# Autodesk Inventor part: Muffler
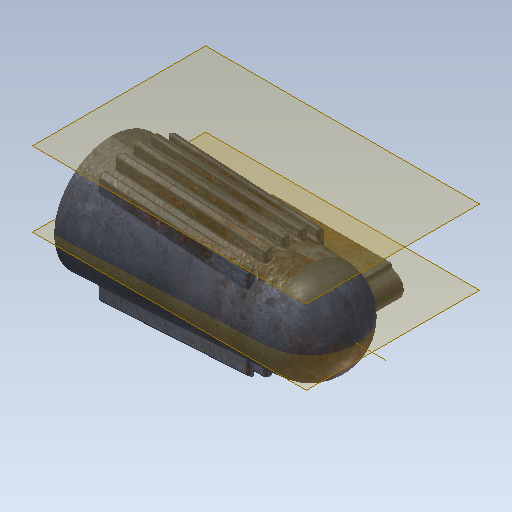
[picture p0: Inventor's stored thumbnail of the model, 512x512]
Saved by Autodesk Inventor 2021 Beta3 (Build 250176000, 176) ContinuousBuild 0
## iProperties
Created: 2012-08
Part Number: Muffler
Material: Aluminum 6061
Document SubType Name: Modeling
Designer: John
Density: 1 g/cm^3
Appearance: Oxidized
Author: John
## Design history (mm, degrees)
sketch "Sketch1"
  geometry: L1 (-24.257, -13.703)-(-24.257, -10.528) reference; L2 (-24.257, -10.528)-(-6.391, -10.528) reference; L3 (-6.391, -10.528)-(-6.391, -13.703) reference; L4 (-6.391, -13.703)-(-24.257, -13.703) reference; L5 (0, -7.62)-(0, -8.89) reference; L6 (0, -7.62)-(-30.48, -7.62) reference; L7 (-30.48, -7.62)-(-30.48, -8.89) reference; L8 (-30.48, -15.24)-(0, -15.24) reference; L9 (-5.756, -9.893)-(-24.892, -9.893); L10 (-24.892, -9.893)-(-24.892, -14.338); L11 (-24.892, -14.338)-(-5.756, -14.338); L12 (-5.756, -14.338)-(-5.756, -9.893); C1 r 1.638 at (0, -12.065) reference; C2 r 1.638 at (-30.48, -12.065) reference; A1 r 3.175 centre (-30.48, -12.065) between (-30.48, -8.89) and (-30.48, -15.24) reference; A2 r 3.175 centre (0, -12.065) between (0, -15.24) and (0, -8.89) reference; 1 further point
  constraints: 8 end point, 3 other
  dimensions: "d0" = 0.635 distance between parallel lines of L9 L2
  node "Reference1"
workplane "Work Plane1"
sketch "Sketch2"
  geometry: L1 (16.653, -4.445)-(-46.049, -4.445); L2 (-46.049, -4.445)-(-46.049, -18.969); L3 (-30.48, -15.24)-(0, -15.24) reference; L4 (-46.049, -18.969)-(5.151, -16.51); A1 r 12.082 centre (4.571, -4.442) between (5.151, -16.51) and (16.653, -4.445); 2 further points
  constraints: 6 end point, 2 point on circle, 1 centre point, 1 perpendicular, 1 tangent, 1 vertical
  dimensions: "d8" = 2.75 deg angle of L3 L4; "d9" = 1.27 distance from line of L3 L4.end; "d12" = 7.62 distance from line of L1 point (0, -12.065)
revolve "Revolution1" sketch "Sketch2" stored, may be unused: angle "d13" = 90 deg
shell "Shell2" dims "d17" = 1.27
extrude "Extrusion1" join sketch "Sketch1" stored distance "d15" = 25.4; taper "d16" = 0 deg
sketch "Sketch3"
  geometry: L1 (5.756, -14.338)-(5.756, -9.893) reference; L2 (5.756, -9.893)-(24.892, -9.893) reference; L3 (24.892, -9.893)-(24.892, -14.338) reference; L4 (24.892, -14.338)-(5.756, -14.338) reference; 1 further point
extrude "Extrusion2" cut sketch "Sketch3" stored distance "d18" = 25.4; taper "d19" = 0 deg
fillet "Fillet1" dims "d20" = 3.175
fillet "Fillet2" dims "d21" = 1.27
fillet "Fillet3" dims "d22" = 1.27
workplane "Work Plane3"
  workplane "Work Plane2"
sketch "Sketch4"
  geometry: L1 (-19.25, 9.843)-(19.25, 9.843); L2 (19.25, 9.843)-(19.25, 7.938); L3 (19.25, 7.938)-(-19.25, 7.938); L4 (-19.25, 7.938)-(-19.25, 9.843); L5 (-19.25, 5.398)-(19.25, 5.398); L6 (19.25, 5.398)-(19.25, 3.493); L7 (19.25, 3.493)-(-19.25, 3.492); L8 (-19.25, 3.492)-(-19.25, 5.398); L9 (-19.25, 0.953)-(19.25, 0.953); L10 (19.25, 0.953)-(19.25, -0.953); L11 (19.25, -0.953)-(-19.25, -0.953); L12 (-19.25, -0.953)-(-19.25, 0.953); L13 (-19.25, -3.493)-(19.25, -3.493); L14 (19.25, -3.493)-(19.25, -5.398); L15 (19.25, -5.398)-(-19.25, -5.398); L16 (-19.25, -5.398)-(-19.25, -3.493); L17 (-19.25, -7.938)-(19.25, -7.938); L18 (19.25, -7.938)-(19.25, -9.843); L19 (19.25, -9.843)-(-19.25, -9.843); L20 (-19.25, -9.843)-(-19.25, -7.938); L21 (-49.642, 0)-(38.14, 0) reference; L22 (25.6, -14.524)-(25.6, 14.524) reference; L23 (-25.6, -12.065)-(-25.6, 12.065) reference; 1 further point
  constraints: 40 end point, 10 parallel, 6 collinear, 6 equal length, 5 horizontal, 5 perpendicular
  dimensions: "d27" = 6.35 distance between parallel lines of L22 L10; "d28" = 6.35 distance between parallel lines of L23 L12 (= d27); "d29" = 2.54 distance between parallel lines of L9 L7; "d30" = 2.54 distance between parallel lines of L13 L11 (= d29); "d31" = 2.54 distance between parallel lines of L3 L5 (= d29); "d32" = 2.54 distance between parallel lines of L17 L15 (= d30); "d33" = 0.9525 distance between parallel lines of L9 L21 (= 0.5 x d34); "d34" = 1.905 distance of L9.end L10.end
emboss "Emboss1" sketch "Sketch4" dims "d25" = 2.54, "d26" = 0
mirror "Mirror2"
fillet "Fillet7" dims "d40" = 0.635
fillet "Fillet8" dims "d41" = 0.508
sketch "Sketch5"
  geometry: A1 r 3.175 centre (0, -12.065) between (-0.907, -9.022) and (0, -15.24) reference; A2 r 3.175 centre (30.48, -12.065) between (30.48, -15.24) and (31.387, -9.022) reference; 1 further point
hole "Hole1" sketch "Sketch5" at (30.48, -12.065), (0, -12.065) diameter "d42" = 2.159; stored, may be unused: countersink angle "d46" = 82 deg, drill point angle "d48" = 118 deg; dims "d43" = 19.05, "d44" = 9.525, "d45" = 6.35, "d47" = 9.525
body "Solid1"
node "Reference2"
workaxis "Work Axis1"
other parameters: "d1" = 25.4, "d23" = 0, "d24" = 19.05
